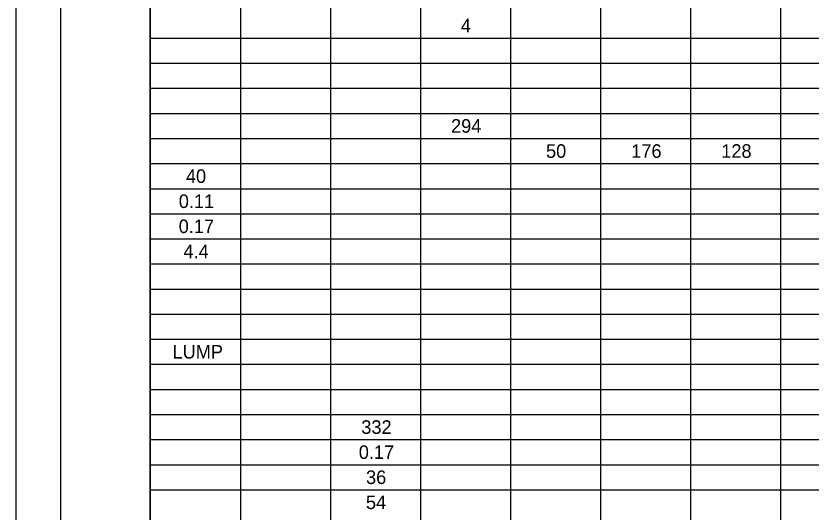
# Model space of a CAD drawing. Extents: x 0 to 34, y 0 to 22.
# Drawn here: x 0 to 8.87, y 10.89 to 16.43 of the extents above; entities that cross this region are included whole.
import ezdxf

# ---------------------------------------------------------------- set-up
doc = ezdxf.new("R2010")
doc.units = 0
for name, color, linetype in [('SH_Border', 7, 'Continuous'), ('SH_Cut_Line', 7, 'Continuous'), ('SH_Text', 7, 'Continuous')]:
    doc.layers.add(name, color=color, linetype=linetype)

msp = doc.modelspace()

# ---------------------------------------------------------------- linework, layer by layer
at = {"layer": 'SH_Border'}
for points in [[(0.5, 21.5), (1.5, 21.5), (1.5, 0.5), (0.5, 0.5)], [(1.5, 21.5), (33.5, 21.5), (33.5, 0.5), (1.5, 0.5)]]:
    msp.add_lwpolyline(points, close=True, dxfattribs=at)
at = {"layer": 'SH_Cut_Line'}
msp.add_lwpolyline([(0, 0), (34, 0), (34, 22), (0, 22)], close=True, dxfattribs=at)
at = {"layer": 'SH_Text'}
for p, q in [((1.5, 21.5), (1.5, 0.5)), ((2.5046, 20.94), (2.5046, 0.5)), ((3.5092, 20.94), (3.5092, 0.5)), ((4.5138, 20.94), (4.5138, 0.5)), ((5.5184, 20.94), (5.5184, 0.5)), ((6.5229, 20.94), (6.5229, 0.5)), ((7.5275, 20.94), (7.5275, 0.5)), ((8.5321, 20.94), (8.5321, 0.5)), ((1.5, 16.18), (32, 16.18)), ((1.5, 15.9), (32, 15.9)), ((1.5, 15.62), (32, 15.62)), ((1.5, 15.34), (32, 15.34)), ((1.5, 15.06), (32, 15.06)), ((1.5, 14.78), (32, 14.78)), ((1.5, 14.5), (32, 14.5)), ((1.5, 14.22), (32, 14.22)), ((1.5, 13.94), (32, 13.94)), ((1.5, 13.66), (32, 13.66)), ((1.5, 13.38), (32, 13.38)), ((1.5, 13.1), (32, 13.1)), ((1.5, 12.82), (32, 12.82)), ((1.5, 12.54), (32, 12.54)), ((1.5, 12.26), (32, 12.26)), ((1.5, 11.98), (32, 11.98)), ((1.5, 11.7), (32, 11.7)), ((1.5, 11.42), (32, 11.42)), ((1.5, 11.14), (32, 11.14))]:
    msp.add_line(p, q, dxfattribs=at)

# ---------------------------------------------------------------- texts
for s, height, p in [('4', 0.1515, (4.9647, 16.2442)), ('294', 0.15153, (4.8559, 15.1242)), ('50', 0.15153, (5.9155, 14.8442)), ('176', 0.15153, (6.8662, 14.8442)), ('128', 0.15153, (7.871, 14.8442)), ('40', 0.15153, (1.8972, 14.5642)), ('0.11', 0.15153, (1.8177, 14.2842)), ('0.17', 0.15153, (1.8168, 14.0042)), ('4.4', 0.15153, (1.8694, 13.7242)), ('LUMP', 0.15153, (1.7479, 12.6042)), ('332', 0.15153, (3.8542, 11.7642)), ('0.17', 0.15153, (3.826, 11.4842)), ('36', 0.15153, (3.9069, 11.2042)), ('54', 0.15153, (3.9057, 10.9242))]:
    msp.add_text(s, height=height, dxfattribs=at).set_placement(p)

doc.saveas('drawing.dxf')
